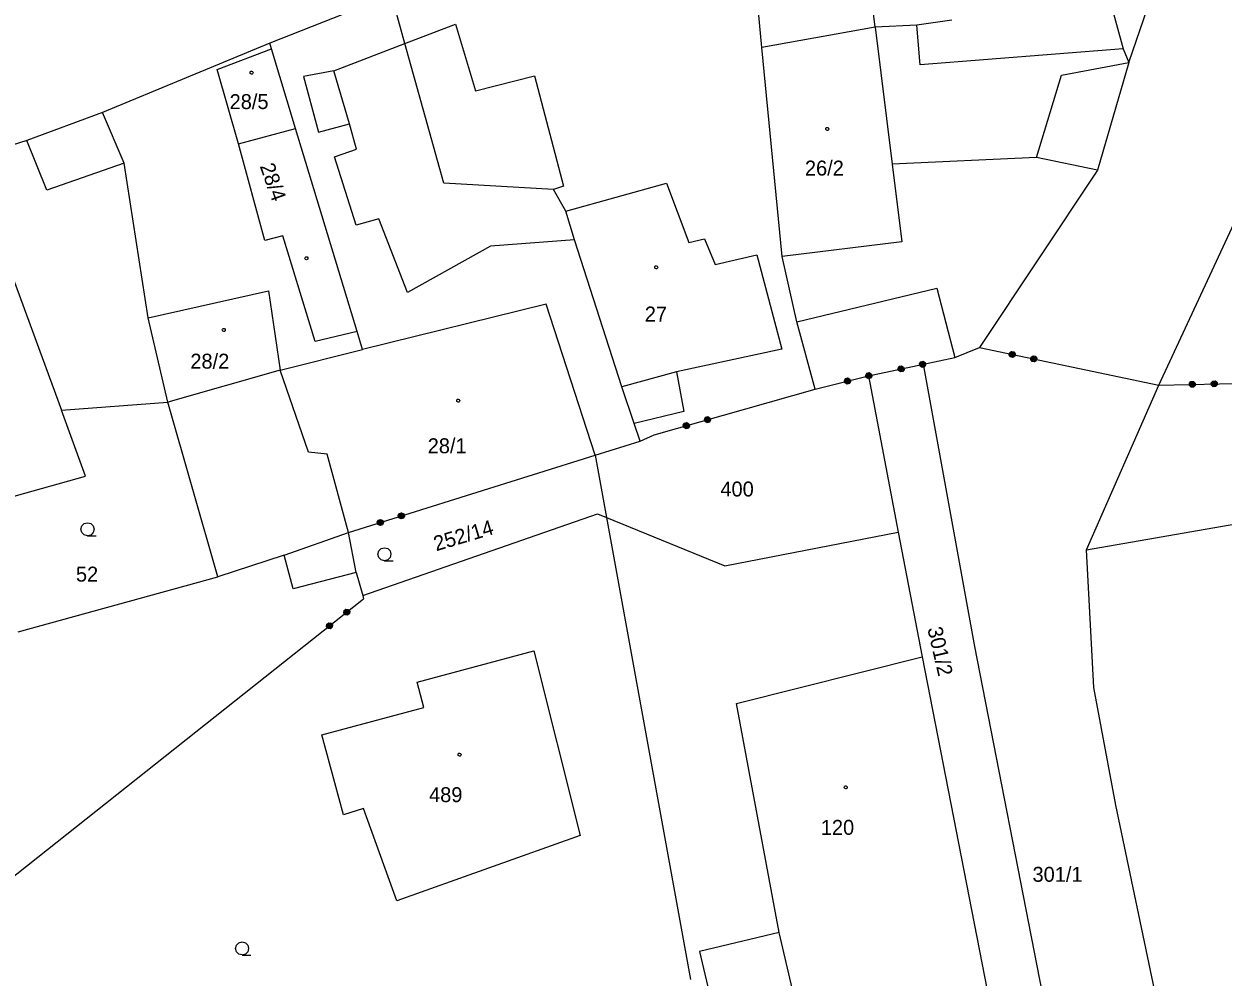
# Model space of a CAD drawing. Extents: x -757994 to -755874, y -1047691 to -1046119.
# Drawn here: x -757541.1 to -757473, y -1047173.7 to -1047119.5 of the extents above; entities that cross this region are included whole.
import ezdxf

# ---------------------------------------------------------------- set-up
doc = ezdxf.new("R2010")
doc.units = 0
doc.layers.add('katastrální mapa', color=7, linetype='Continuous')

msp = doc.modelspace()

# ---------------------------------------------------------------- linework, layer by layer
at = {"layer": 'katastrální mapa'}
for p, q in [((-757492.76, -1047119.64), (-757493.94, -1047109.62)), ((-757499.19, -1047120.79), (-757500.23, -1047109.94)), ((-757478.33, -1047121.66), (-757476.47, -1047116.22)), ((-757520.24, -1047117.82), (-757527.17, -1047120.55)), ((-757519.48, -1047120.57), (-757520.24, -1047117.82)), ((-757479.42, -1047118.08), (-757478.66, -1047120.87)), ((-757519.48, -1047120.57), (-757516.6, -1047119.47)), ((-757516.6, -1047119.47), (-757515.48, -1047123.27)), ((-757492.76, -1047119.64), (-757499.19, -1047120.79)), ((-757490.38, -1047119.52), (-757492.76, -1047119.64)), ((-757492.76, -1047119.64), (-757491.78, -1047127.43)), ((-757488.39, -1047119.25), (-757490.38, -1047119.52)), ((-757490.19, -1047121.79), (-757490.38, -1047119.52)), ((-757527.17, -1047120.55), (-757536.67, -1047124.5)), ((-757527.07, -1047120.88), (-757527.17, -1047120.55)), ((-757525.7, -1047125.41), (-757527.07, -1047120.88)), ((-757523.53, -1047122.12), (-757519.48, -1047120.57)), ((-757517.27, -1047128.52), (-757519.48, -1047120.57)), ((-757498.04, -1047132.69), (-757499.19, -1047120.79)), ((-757478.66, -1047120.87), (-757490.19, -1047121.79)), ((-757478.66, -1047120.87), (-757478.33, -1047121.66)), ((-757482.17, -1047122.37), (-757478.33, -1047121.66)), ((-757478.33, -1047121.66), (-757480.11, -1047127.77)), ((-757523.53, -1047122.12), (-757525.24, -1047122.45)), ((-757525.24, -1047122.45), (-757524.4, -1047125.61)), ((-757522.63, -1047125.13), (-757523.53, -1047122.12)), ((-757515.48, -1047123.27), (-757512.12, -1047122.4)), ((-757512.12, -1047122.4), (-757510.46, -1047128.69)), ((-757483.58, -1047127.06), (-757482.17, -1047122.37)), ((-757536.67, -1047124.5), (-757540.98, -1047126.09)), ((-757535.44, -1047127.37), (-757536.67, -1047124.5)), ((-757524.4, -1047125.61), (-757522.63, -1047125.13)), ((-757522.24, -1047126.57), (-757522.63, -1047125.13)), ((-757528.94, -1047126.27), (-757525.7, -1047125.41)), ((-757522.2, -1047136.94), (-757525.7, -1047125.41)), ((-757540.98, -1047126.09), (-757544.26, -1047127.12)), ((-757539.83, -1047128.92), (-757540.98, -1047126.09)), ((-757523.48, -1047127.02), (-757522.24, -1047126.57)), ((-757544.26, -1047127.12), (-757539.01, -1047141.42)), ((-757522.25, -1047130.9), (-757523.48, -1047127.02)), ((-757483.58, -1047127.06), (-757491.78, -1047127.43)), ((-757480.11, -1047127.77), (-757483.58, -1047127.06)), ((-757535.44, -1047127.37), (-757539.83, -1047128.92)), ((-757534.07, -1047136.17), (-757535.44, -1047127.37)), ((-757491.78, -1047127.43), (-757491.23, -1047131.85)), ((-757480.11, -1047127.77), (-757486.82, -1047137.86)), ((-757511.03, -1047128.88), (-757517.27, -1047128.52)), ((-757510.46, -1047128.69), (-757511.03, -1047128.88)), ((-757510.34, -1047130.1), (-757504.62, -1047128.51)), ((-757504.62, -1047128.51), (-757503.35, -1047131.88)), ((-757510.34, -1047130.1), (-757511.03, -1047128.88)), ((-757520.97, -1047130.54), (-757522.25, -1047130.9)), ((-757519.33, -1047134.73), (-757520.97, -1047130.54)), ((-757509.84, -1047131.74), (-757510.34, -1047130.1)), ((-757476.63, -1047139.99), (-757472.35, -1047130.79)), ((-757514.61, -1047132.09), (-757519.33, -1047134.73)), ((-757509.84, -1047131.74), (-757514.61, -1047132.09)), ((-757507.16, -1047140.09), (-757509.84, -1047131.74)), ((-757503.35, -1047131.88), (-757502.45, -1047131.68)), ((-757502.45, -1047131.68), (-757501.85, -1047133.13)), ((-757491.23, -1047131.85), (-757498.04, -1047132.69)), ((-757501.85, -1047133.13), (-757499.48, -1047132.58)), ((-757499.48, -1047132.58), (-757498.06, -1047137.96)), ((-757497.2, -1047136.39), (-757498.04, -1047132.69)), ((-757534.07, -1047136.17), (-757527.24, -1047134.64)), ((-757527.24, -1047134.64), (-757526.58, -1047139.15)), ((-757497.2, -1047136.39), (-757489.24, -1047134.48)), ((-757489.24, -1047134.48), (-757488.23, -1047138.43)), ((-757511.45, -1047135.39), (-757521.89, -1047137.98)), ((-757508.67, -1047143.98), (-757511.45, -1047135.39)), ((-757532.96, -1047140.97), (-757534.07, -1047136.17)), ((-757496.17, -1047140.22), (-757497.2, -1047136.39)), ((-757521.89, -1047137.98), (-757522.2, -1047136.94)), ((-757526.58, -1047139.15), (-757521.89, -1047137.98)), ((-757498.06, -1047137.96), (-757504.04, -1047139.25)), ((-757488.23, -1047138.43), (-757486.82, -1047137.86)), ((-757486.82, -1047137.86), (-757476.63, -1047139.99)), ((-757493.14, -1047139.46), (-757490.01, -1047138.8)), ((-757490.01, -1047138.8), (-757488.23, -1047138.43)), ((-757487.09, -1047154.86), (-757490.01, -1047138.8)), ((-757526.58, -1047139.15), (-757532.96, -1047140.97)), ((-757524.97, -1047143.81), (-757526.58, -1047139.15)), ((-757504.04, -1047139.25), (-757507.16, -1047140.09)), ((-757504.04, -1047139.25), (-757503.63, -1047141.49)), ((-757496.17, -1047140.22), (-757493.14, -1047139.46)), ((-757493.14, -1047139.46), (-757491.44, -1047148.35)), ((-757476.63, -1047139.99), (-757452.44, -1047139.46)), ((-757506.46, -1047142.17), (-757507.16, -1047140.09)), ((-757505.31, -1047142.82), (-757496.17, -1047140.22)), ((-757480.75, -1047149.36), (-757476.63, -1047139.99)), ((-757539.01, -1047141.42), (-757532.96, -1047140.97)), ((-757530.12, -1047150.9), (-757532.96, -1047140.97)), ((-757537.63, -1047145.17), (-757539.01, -1047141.42)), ((-757503.63, -1047141.49), (-757506.46, -1047142.17)), ((-757506.12, -1047143.18), (-757506.46, -1047142.17)), ((-757506.12, -1047143.18), (-757505.31, -1047142.82)), ((-757508.67, -1047143.98), (-757506.12, -1047143.18)), ((-757523.9, -1047143.92), (-757524.97, -1047143.81)), ((-757522.69, -1047148.37), (-757523.9, -1047143.92)), ((-757522.69, -1047148.37), (-757508.67, -1047143.98)), ((-757508.67, -1047143.98), (-757508.03, -1047147.52)), ((-757544.1, -1047146.98), (-757537.63, -1047145.17)), ((-757521.88, -1047151.96), (-757508.54, -1047147.31)), ((-757508.54, -1047147.31), (-757508.03, -1047147.52)), ((-757508.03, -1047147.52), (-757503.25, -1047173.8)), ((-757508.03, -1047147.52), (-757501.3, -1047150.28)), ((-757526.34, -1047149.66), (-757522.69, -1047148.37)), ((-757522.26, -1047150.66), (-757522.69, -1047148.37)), ((-757501.3, -1047150.28), (-757491.44, -1047148.35)), ((-757491.44, -1047148.35), (-757490.09, -1047155.45)), ((-757480.75, -1047149.36), (-757472.26, -1047147.88)), ((-757526.34, -1047149.66), (-757530.12, -1047150.9)), ((-757525.83, -1047151.58), (-757526.34, -1047149.66)), ((-757480.33, -1047157.2), (-757480.75, -1047149.36)), ((-757541.46, -1047154.03), (-757530.12, -1047150.9)), ((-757522.26, -1047150.66), (-757525.83, -1047151.58)), ((-757522.26, -1047150.66), (-757521.88, -1047151.96)), ((-757548.75, -1047173.51), (-757521.83, -1047152.14)), ((-757521.88, -1047151.96), (-757521.83, -1047152.14)), ((-757518.79, -1047156.89), (-757512.16, -1047155.11)), ((-757512.16, -1047155.11), (-757509.53, -1047165.61)), ((-757483.24, -1047174.58), (-757487.09, -1047154.86)), ((-757500.63, -1047158.11), (-757490.09, -1047155.45)), ((-757490.09, -1047155.45), (-757486.24, -1047175.17)), ((-757518.4, -1047158.33), (-757518.79, -1047156.89)), ((-757479.08, -1047163.89), (-757480.33, -1047157.2)), ((-757524.2, -1047159.88), (-757518.4, -1047158.33)), ((-757498.21, -1047171.13), (-757500.63, -1047158.11)), ((-757522.98, -1047164.44), (-757524.2, -1047159.88)), ((-757521.83, -1047164.07), (-757522.98, -1047164.44)), ((-757519.94, -1047169.32), (-757521.83, -1047164.07)), ((-757472.48, -1047195.25), (-757479.08, -1047163.89)), ((-757509.53, -1047165.61), (-757519.94, -1047169.32)), ((-757498.21, -1047171.13), (-757502.74, -1047172.2)), ((-757496.77, -1047177.28), (-757498.21, -1047171.13)), ((-757502.74, -1047172.2), (-757501.11, -1047179.11))]:
    msp.add_line(p, q, dxfattribs=at)
for points in [[(-757528.94, -1047126.27), (-757530.16, -1047122.04), (-757527.07, -1047120.88)], [(-757522.2, -1047136.94), (-757524.59, -1047137.52), (-757526.43, -1047131.5), (-757527.45, -1047131.78), (-757528.94, -1047126.27)], [(-757484.864, -1047138.105), (-757484.79, -1047138.218), (-757484.818, -1047138.35), (-757484.93, -1047138.423), (-757485.062, -1047138.396), (-757485.136, -1047138.283), (-757485.108, -1047138.151), (-757484.996, -1047138.078), (-757484.864, -1047138.105), (-757484.873, -1047138.124), (-757484.99, -1047138.099), (-757485.038, -1047138.13), (-757484.842, -1047138.171), (-757484.811, -1047138.219), (-757485.085, -1047138.161), (-757485.093, -1047138.2), (-757484.819, -1047138.258), (-757484.827, -1047138.297), (-757485.101, -1047138.24), (-757485.109, -1047138.279), (-757484.835, -1047138.336), (-757484.883, -1047138.367), (-757485.079, -1047138.326), (-757485.048, -1047138.373), (-757484.93, -1047138.398)], [(-757491.25, -1047138.898), (-757491.138, -1047138.971), (-757491.11, -1047139.104), (-757491.183, -1047139.216), (-757491.315, -1047139.244), (-757491.428, -1047139.171), (-757491.456, -1047139.039), (-757491.382, -1047138.926), (-757491.25, -1047138.898), (-757491.251, -1047138.919), (-757491.368, -1047138.943), (-757491.399, -1047138.991), (-757491.204, -1047138.95), (-757491.156, -1047138.98), (-757491.43, -1047139.038), (-757491.422, -1047139.077), (-757491.148, -1047139.02), (-757491.14, -1047139.059), (-757491.414, -1047139.117), (-757491.405, -1047139.156), (-757491.131, -1047139.098), (-757491.162, -1047139.145), (-757491.358, -1047139.187), (-757491.311, -1047139.217), (-757491.193, -1047139.193)], [(-757490.027, -1047138.64), (-757489.915, -1047138.713), (-757489.887, -1047138.845), (-757489.96, -1047138.958), (-757490.092, -1047138.986), (-757490.205, -1047138.913), (-757490.233, -1047138.78), (-757490.159, -1047138.668), (-757490.027, -1047138.64), (-757490.038, -1047138.663), (-757490.155, -1047138.687), (-757490.186, -1047138.735), (-757489.99, -1047138.694), (-757489.943, -1047138.724), (-757490.217, -1047138.782), (-757490.209, -1047138.821), (-757489.935, -1047138.764), (-757489.926, -1047138.803), (-757490.2, -1047138.861), (-757490.192, -1047138.9), (-757489.918, -1047138.842), (-757489.949, -1047138.889), (-757490.145, -1047138.931), (-757490.097, -1047138.961), (-757489.98, -1047138.937)], [(-757483.64, -1047138.361), (-757483.567, -1047138.474), (-757483.594, -1047138.606), (-757483.707, -1047138.679), (-757483.839, -1047138.652), (-757483.912, -1047138.539), (-757483.885, -1047138.407), (-757483.772, -1047138.334), (-757483.64, -1047138.361), (-757483.659, -1047138.378), (-757483.777, -1047138.353), (-757483.824, -1047138.384), (-757483.628, -1047138.425), (-757483.597, -1047138.472), (-757483.871, -1047138.415), (-757483.879, -1047138.454), (-757483.605, -1047138.512), (-757483.614, -1047138.551), (-757483.888, -1047138.493), (-757483.896, -1047138.533), (-757483.622, -1047138.59), (-757483.669, -1047138.621), (-757483.865, -1047138.58), (-757483.834, -1047138.627), (-757483.716, -1047138.652)], [(-757494.303, -1047139.587), (-757494.188, -1047139.656), (-757494.155, -1047139.787), (-757494.224, -1047139.902), (-757494.355, -1047139.935), (-757494.47, -1047139.866), (-757494.503, -1047139.735), (-757494.434, -1047139.62), (-757494.303, -1047139.587), (-757494.303, -1047139.607), (-757494.419, -1047139.637), (-757494.448, -1047139.685), (-757494.254, -1047139.637), (-757494.206, -1047139.666), (-757494.477, -1047139.734), (-757494.468, -1047139.773), (-757494.196, -1047139.704), (-757494.186, -1047139.743), (-757494.458, -1047139.811), (-757494.448, -1047139.85), (-757494.177, -1047139.782), (-757494.206, -1047139.831), (-757494.4, -1047139.879), (-757494.351, -1047139.908), (-757494.235, -1047139.879)], [(-757493.091, -1047139.282), (-757492.975, -1047139.351), (-757492.942, -1047139.482), (-757493.011, -1047139.598), (-757493.142, -1047139.631), (-757493.258, -1047139.562), (-757493.291, -1047139.431), (-757493.222, -1047139.315), (-757493.091, -1047139.282), (-757493.1, -1047139.306), (-757493.217, -1047139.335), (-757493.246, -1047139.383), (-757493.052, -1047139.335), (-757493.003, -1047139.364), (-757493.275, -1047139.432), (-757493.265, -1047139.471), (-757492.993, -1047139.402), (-757492.984, -1047139.441), (-757493.255, -1047139.509), (-757493.246, -1047139.548), (-757492.974, -1047139.48), (-757493.003, -1047139.529), (-757493.197, -1047139.577), (-757493.148, -1047139.606), (-757493.032, -1047139.577)], [(-757474.669, -1047139.787), (-757474.572, -1047139.88), (-757474.569, -1047140.015), (-757474.662, -1047140.112), (-757474.797, -1047140.115), (-757474.894, -1047140.022), (-757474.897, -1047139.887), (-757474.804, -1047139.79), (-757474.669, -1047139.787), (-757474.674, -1047139.807), (-757474.794, -1047139.81), (-757474.833, -1047139.851), (-757474.633, -1047139.846), (-757474.592, -1047139.885), (-757474.872, -1047139.892), (-757474.871, -1047139.932), (-757474.591, -1047139.925), (-757474.59, -1047139.965), (-757474.87, -1047139.972), (-757474.869, -1047140.012), (-757474.589, -1047140.005), (-757474.628, -1047140.046), (-757474.828, -1047140.051), (-757474.787, -1047140.09), (-757474.667, -1047140.087)], [(-757473.419, -1047139.76), (-757473.322, -1047139.852), (-757473.319, -1047139.987), (-757473.412, -1047140.084), (-757473.547, -1047140.087), (-757473.644, -1047139.995), (-757473.647, -1047139.86), (-757473.554, -1047139.763), (-757473.419, -1047139.76), (-757473.434, -1047139.78), (-757473.554, -1047139.783), (-757473.593, -1047139.823), (-757473.393, -1047139.819), (-757473.352, -1047139.858), (-757473.632, -1047139.864), (-757473.631, -1047139.904), (-757473.351, -1047139.898), (-757473.35, -1047139.938), (-757473.63, -1047139.944), (-757473.629, -1047139.984), (-757473.349, -1047139.978), (-757473.389, -1047140.019), (-757473.589, -1047140.023), (-757473.548, -1047140.062), (-757473.428, -1047140.06)], [(-757503.464, -1047142.128), (-757503.346, -1047142.194), (-757503.309, -1047142.324), (-757503.375, -1047142.441), (-757503.505, -1047142.478), (-757503.622, -1047142.413), (-757503.659, -1047142.283), (-757503.594, -1047142.165), (-757503.464, -1047142.128), (-757503.463, -1047142.149), (-757503.579, -1047142.182), (-757503.606, -1047142.231), (-757503.414, -1047142.177), (-757503.364, -1047142.204), (-757503.634, -1047142.281), (-757503.623, -1047142.319), (-757503.353, -1047142.243), (-757503.342, -1047142.281), (-757503.612, -1047142.358), (-757503.601, -1047142.396), (-757503.331, -1047142.319), (-757503.359, -1047142.369), (-757503.551, -1047142.424), (-757503.502, -1047142.451), (-757503.387, -1047142.418)], [(-757502.261, -1047141.787), (-757502.144, -1047141.852), (-757502.107, -1047141.982), (-757502.173, -1047142.099), (-757502.302, -1047142.136), (-757502.42, -1047142.071), (-757502.457, -1047141.941), (-757502.391, -1047141.823), (-757502.261, -1047141.787), (-757502.27, -1047141.81), (-757502.386, -1047141.843), (-757502.413, -1047141.892), (-757502.221, -1047141.837), (-757502.172, -1047141.865), (-757502.441, -1047141.942), (-757502.43, -1047141.98), (-757502.161, -1047141.903), (-757502.15, -1047141.942), (-757502.419, -1047142.018), (-757502.408, -1047142.057), (-757502.139, -1047141.98), (-757502.166, -1047142.03), (-757502.359, -1047142.084), (-757502.309, -1047142.112), (-757502.194, -1047142.079)], [(-757520.863, -1047147.63), (-757520.744, -1047147.692), (-757520.703, -1047147.821), (-757520.766, -1047147.94), (-757520.894, -1047147.98), (-757521.013, -1047147.918), (-757521.054, -1047147.789), (-757520.991, -1047147.67), (-757520.863, -1047147.63), (-757520.861, -1047147.65), (-757520.976, -1047147.686), (-757521.002, -1047147.736), (-757520.811, -1047147.677), (-757520.761, -1047147.703), (-757521.028, -1047147.786), (-757521.016, -1047147.825), (-757520.749, -1047147.741), (-757520.737, -1047147.779), (-757521.005, -1047147.863), (-757520.993, -1047147.901), (-757520.725, -1047147.817), (-757520.752, -1047147.868), (-757520.942, -1047147.927), (-757520.892, -1047147.954), (-757520.778, -1047147.918)], [(-757519.67, -1047147.257), (-757519.551, -1047147.319), (-757519.51, -1047147.448), (-757519.573, -1047147.567), (-757519.701, -1047147.607), (-757519.82, -1047147.545), (-757519.861, -1047147.416), (-757519.798, -1047147.297), (-757519.67, -1047147.257), (-757519.678, -1047147.28), (-757519.792, -1047147.316), (-757519.819, -1047147.366), (-757519.628, -1047147.307), (-757519.578, -1047147.333), (-757519.845, -1047147.416), (-757519.833, -1047147.455), (-757519.566, -1047147.371), (-757519.554, -1047147.409), (-757519.821, -1047147.493), (-757519.809, -1047147.531), (-757519.542, -1047147.447), (-757519.568, -1047147.498), (-757519.759, -1047147.557), (-757519.709, -1047147.584), (-757519.594, -1047147.548)], [(-757537.52, -1047148.56), (-757537.71, -1047148.51), (-757537.845, -1047148.375), (-757537.895, -1047148.19), (-757537.845, -1047148.005), (-757537.71, -1047147.87), (-757537.525, -1047147.82), (-757537.34, -1047147.87), (-757537.205, -1047148.005), (-757537.155, -1047148.195), (-757537.205, -1047148.385), (-757537.34, -1047148.52), (-757537.53, -1047148.57), (-757537.03, -1047148.57)], [(-757520.64, -1047149.98), (-757520.83, -1047149.93), (-757520.965, -1047149.795), (-757521.015, -1047149.61), (-757520.965, -1047149.425), (-757520.83, -1047149.29), (-757520.645, -1047149.24), (-757520.46, -1047149.29), (-757520.325, -1047149.425), (-757520.275, -1047149.615), (-757520.325, -1047149.805), (-757520.46, -1047149.94), (-757520.65, -1047149.99), (-757520.15, -1047149.99)], [(-757522.835, -1047152.733), (-757522.701, -1047152.749), (-757522.617, -1047152.854), (-757522.633, -1047152.988), (-757522.739, -1047153.072), (-757522.872, -1047153.057), (-757522.956, -1047152.951), (-757522.941, -1047152.817), (-757522.835, -1047152.733), (-757522.834, -1047152.758), (-757522.928, -1047152.833), (-757522.935, -1047152.889), (-757522.778, -1047152.765), (-757522.722, -1047152.771), (-757522.941, -1047152.945), (-757522.916, -1047152.977), (-757522.697, -1047152.803), (-757522.672, -1047152.834), (-757522.891, -1047153.008), (-757522.866, -1047153.039), (-757522.647, -1047152.865), (-757522.654, -1047152.921), (-757522.81, -1047153.046), (-757522.754, -1047153.052), (-757522.66, -1047152.978)], [(-757523.814, -1047153.511), (-757523.68, -1047153.526), (-757523.596, -1047153.632), (-757523.612, -1047153.765), (-757523.718, -1047153.849), (-757523.851, -1047153.834), (-757523.935, -1047153.728), (-757523.92, -1047153.595), (-757523.814, -1047153.511), (-757523.805, -1047153.529), (-757523.899, -1047153.604), (-757523.906, -1047153.66), (-757523.749, -1047153.536), (-757523.693, -1047153.542), (-757523.912, -1047153.716), (-757523.887, -1047153.748), (-757523.668, -1047153.574), (-757523.643, -1047153.605), (-757523.863, -1047153.779), (-757523.838, -1047153.81), (-757523.618, -1047153.636), (-757523.625, -1047153.692), (-757523.781, -1047153.817), (-757523.725, -1047153.823), (-757523.631, -1047153.749)], [(-757528.73, -1047172.4), (-757528.92, -1047172.35), (-757529.055, -1047172.215), (-757529.105, -1047172.03), (-757529.055, -1047171.845), (-757528.92, -1047171.71), (-757528.735, -1047171.66), (-757528.55, -1047171.71), (-757528.415, -1047171.845), (-757528.365, -1047172.035), (-757528.415, -1047172.225), (-757528.55, -1047172.36), (-757528.74, -1047172.41), (-757528.24, -1047172.41)]]:
    msp.add_lwpolyline(points, dxfattribs=at)
for points in [[(-757528.2, -1047122.145), (-757528.15, -1047122.155), (-757528.125, -1047122.2), (-757528.115, -1047122.23), (-757528.125, -1047122.275), (-757528.165, -1047122.31), (-757528.2, -1047122.315), (-757528.245, -1047122.3), (-757528.275, -1047122.27), (-757528.285, -1047122.23), (-757528.275, -1047122.185), (-757528.235, -1047122.15)], [(-757495.48, -1047125.345), (-757495.43, -1047125.355), (-757495.405, -1047125.4), (-757495.395, -1047125.43), (-757495.405, -1047125.475), (-757495.445, -1047125.51), (-757495.48, -1047125.515), (-757495.525, -1047125.5), (-757495.555, -1047125.47), (-757495.565, -1047125.43), (-757495.555, -1047125.385), (-757495.515, -1047125.35)], [(-757525.08, -1047132.695), (-757525.03, -1047132.705), (-757525.005, -1047132.75), (-757524.995, -1047132.78), (-757525.005, -1047132.825), (-757525.045, -1047132.86), (-757525.08, -1047132.865), (-757525.125, -1047132.85), (-757525.155, -1047132.82), (-757525.165, -1047132.78), (-757525.155, -1047132.735), (-757525.115, -1047132.7)], [(-757505.2, -1047133.215), (-757505.15, -1047133.225), (-757505.125, -1047133.27), (-757505.115, -1047133.3), (-757505.125, -1047133.345), (-757505.165, -1047133.38), (-757505.2, -1047133.385), (-757505.245, -1047133.37), (-757505.275, -1047133.34), (-757505.285, -1047133.3), (-757505.275, -1047133.255), (-757505.235, -1047133.22)], [(-757529.78, -1047136.775), (-757529.73, -1047136.785), (-757529.705, -1047136.83), (-757529.695, -1047136.86), (-757529.705, -1047136.905), (-757529.745, -1047136.94), (-757529.78, -1047136.945), (-757529.825, -1047136.93), (-757529.855, -1047136.9), (-757529.865, -1047136.86), (-757529.855, -1047136.815), (-757529.815, -1047136.78)], [(-757516.45, -1047140.795), (-757516.4, -1047140.805), (-757516.375, -1047140.85), (-757516.365, -1047140.88), (-757516.375, -1047140.925), (-757516.415, -1047140.96), (-757516.45, -1047140.965), (-757516.495, -1047140.95), (-757516.525, -1047140.92), (-757516.535, -1047140.88), (-757516.525, -1047140.835), (-757516.485, -1047140.8)], [(-757516.38, -1047160.925), (-757516.33, -1047160.935), (-757516.305, -1047160.98), (-757516.295, -1047161.01), (-757516.305, -1047161.055), (-757516.345, -1047161.09), (-757516.38, -1047161.095), (-757516.425, -1047161.08), (-757516.455, -1047161.05), (-757516.465, -1047161.01), (-757516.455, -1047160.965), (-757516.415, -1047160.93)], [(-757494.43, -1047162.785), (-757494.38, -1047162.795), (-757494.355, -1047162.84), (-757494.345, -1047162.87), (-757494.355, -1047162.915), (-757494.395, -1047162.95), (-757494.43, -1047162.955), (-757494.475, -1047162.94), (-757494.505, -1047162.91), (-757494.515, -1047162.87), (-757494.505, -1047162.825), (-757494.465, -1047162.79)]]:
    msp.add_lwpolyline(points, close=True, dxfattribs=at)

# ---------------------------------------------------------------- texts
for s, rotation, p in [('28/5', 0.17189, (-757529.446, -1047124.304)), ('28/4', 289.45828, (-757527.744, -1047127.539)), ('252/14', 16.55848, (-757517.706, -1047149.446)), ('301/2', 283.04115, (-757489.793, -1047153.836))]:
    msp.add_text(s, height=0.85, rotation=rotation, dxfattribs=at).set_placement(p)
for s, p in [('26/2', (-757496.746, -1047128.08)), ('27', (-757505.849, -1047136.38)), ('28/2', (-757531.679, -1047139.06)), ('28/1', (-757518.188, -1047143.87)), ('400', (-757501.551, -1047146.33)), ('52', (-757538.183, -1047151.17)), ('489', (-757518.111, -1047163.71)), ('120', (-757495.844, -1047165.57)), ('301/1', (-757483.811, -1047168.24))]:
    msp.add_text(s, height=0.85, dxfattribs=at).set_placement(p)

doc.saveas('drawing.dxf')
